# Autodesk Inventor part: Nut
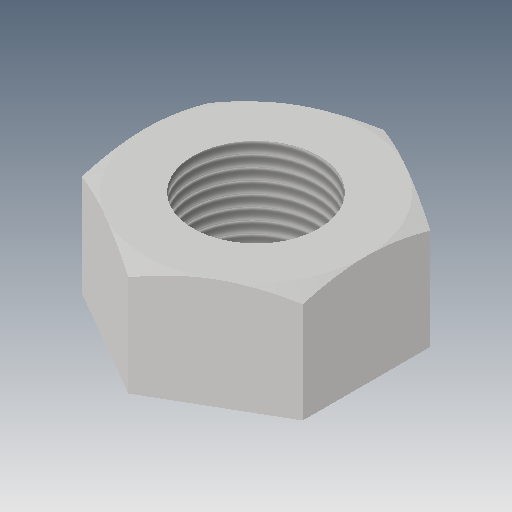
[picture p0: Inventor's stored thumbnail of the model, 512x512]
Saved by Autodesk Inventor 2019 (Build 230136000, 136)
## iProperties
Created: 2016-05
Part Number: Nut
Material: Generic
Document SubType Name: Modeling
Designer: CADCIM
Density: 1 g/cm^3
Appearance: Default
Author: CADCIM
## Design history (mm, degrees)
sketch "Sketch1"
  geometry: L1 (0, -33.255)-(-28.8, -16.628); L2 (-28.8, -16.628)-(-28.8, 16.628); L3 (-28.8, 16.628)-(0, 33.255); L4 (0, 33.255)-(28.8, 16.628); L5 (28.8, 16.628)-(28.8, -16.628); L6 (28.8, -16.628)-(0, -33.255); 2 further points
  constraints: 12 end point, 1 coincident, 13 other
  dimensions: "d0" = 57.6 distance between parallel lines of L2 L5
extrude "Extrusion1" new body sketch "Sketch1" stored distance "d1" = 28.8; taper "d2" = 0 deg
sketch "Sketch2"
  geometry: L1 (0, 33.255)-(-28.8, 16.628) reference; C1 r 28.8 at (0, 0); 1 further point
  constraints: 1 centre point, 1 coincident, 1 tangent
extrude "Extrusion2" sketch "Sketch2" distance "d3" = 28.8; taper "d4" = 60 deg
sketch "Sketch3"
  geometry: 1 further point
hole "Hole1" diameter "d7" = 32.752; stored, may be unused: countersink angle "d11" = 90 deg, drill point angle "d13" = 118 deg; dims "d5" = 10, "d6" = 10, "d8" = 72, "d9" = 4, "d10" = 2, "d12" = 85.1
body "Solid1"
